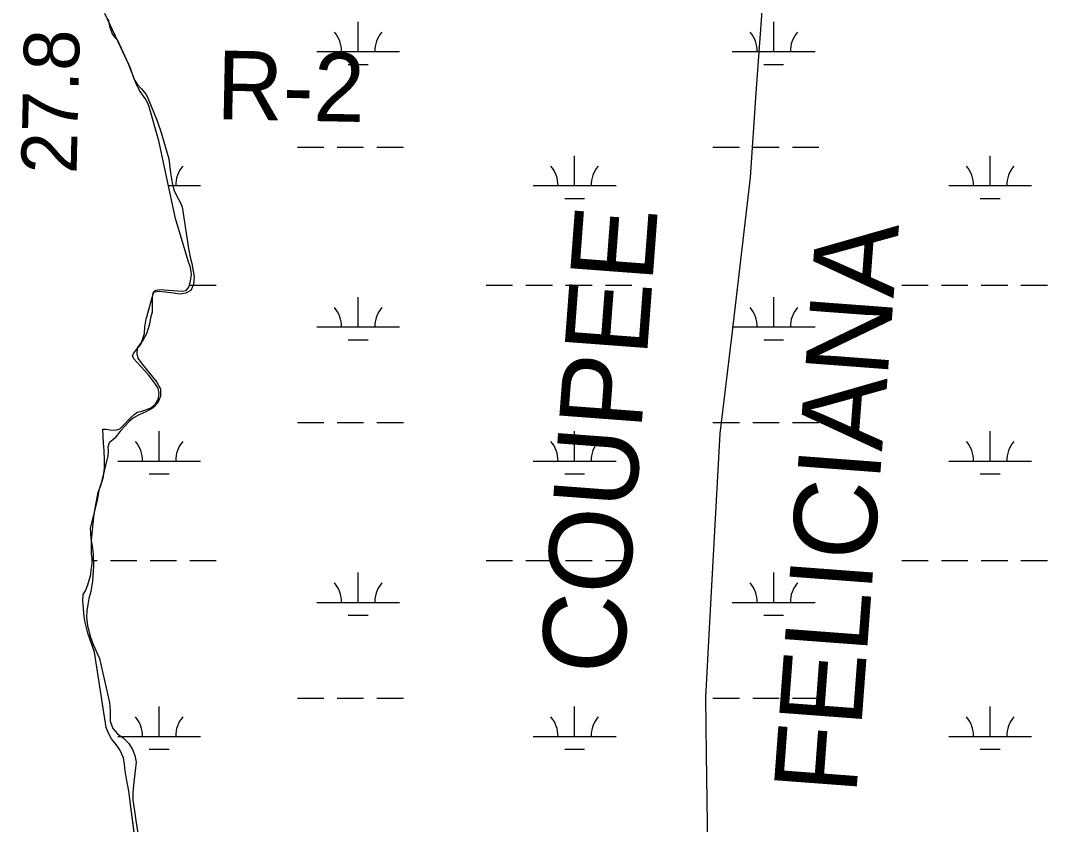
# Model space of a CAD drawing. Extents: x 3161564 to 3199464, y 849354 to 874788.
# Drawn here: x 3176988 to 3178229, y 863719 to 864690 of the extents above; entities that cross this region are included whole.
import ezdxf

# ---------------------------------------------------------------- set-up
doc = ezdxf.new("R2010")
doc.units = 0
for name, color, linetype in [('V-RIVR-RANG', 7, 'Continuous'), ('V-RIVR-RANG-IDEN', 7, 'Continuous'), ('V-SITE-VEGE', 7, 'Continuous'), ('V-TOPO-BNDY', 7, 'Continuous'), ('V-TOPO-GNAM-IDEN', 7, 'Continuous'), ('V-TOPO-SHOR', 7, 'Continuous'), ('V-WETL-SWMP', 7, 'Continuous')]:
    doc.layers.add(name, color=color, linetype=linetype)

msp = doc.modelspace()

# ---------------------------------------------------------------- linework, layer by layer
at = {"layer": 'V-SITE-VEGE'}
for p, q in [((3177094.1, 864691.9), (3177095.6, 864683.6)), ((3177095.6, 864683.6), (3177099, 864674.3)), ((3177099, 864674.3), (3177103, 864668.9)), ((3177103, 864668.9), (3177105.4, 864666.5)), ((3177105.4, 864666.5), (3177120.5, 864633.3)), ((3177120.5, 864633.3), (3177125.1, 864619.8)), ((3177125.1, 864619.8), (3177129.2, 864613.3)), ((3177129.2, 864613.3), (3177134.2, 864607.9)), ((3177134.2, 864607.9), (3177139.8, 864601)), ((3177139.8, 864601), (3177142.5, 864595.6)), ((3177142.5, 864595.6), (3177152.6, 864571)), ((3177152.6, 864571), (3177157.2, 864557.5)), ((3177157.2, 864557.5), (3177167.2, 864523.2)), ((3177167.2, 864523.2), (3177169.4, 864506.2)), ((3177169.4, 864506.2), (3177171.2, 864494.3)), ((3177171.2, 864494.3), (3177173.2, 864485.9)), ((3177173.2, 864485.9), (3177176.9, 864478)), ((3177176.9, 864478), (3177180.9, 864470.8)), ((3177180.9, 864470.8), (3177183.5, 864465.1)), ((3177183.5, 864465.1), (3177191, 864415)), ((3177191, 864415), (3177193, 864404.3)), ((3177193, 864404.3), (3177195.2, 864396.9)), ((3177195.2, 864396.9), (3177196.7, 864387.7)), ((3177196.7, 864387.7), (3177198.1, 864380.5)), ((3177198.1, 864380.5), (3177197, 864371.3)), ((3177197, 864371.3), (3177193.9, 864364.3)), ((3177147.3, 864354.9), (3177147.1, 864337.9)), ((3177147.9, 864361.2), (3177147.3, 864354.9)), ((3177150, 864362.1), (3177147.9, 864361.2)), ((3177156, 864363), (3177150, 864362.1)), ((3177173, 864361.1), (3177156, 864363)), ((3177180.7, 864359.8), (3177173, 864361.1)), ((3177187.7, 864360.9), (3177180.7, 864359.8)), ((3177193.9, 864364.3), (3177187.7, 864360.9)), ((3177145.4, 864331.1), (3177144.1, 864323.6)), ((3177147.1, 864337.9), (3177145.4, 864331.1)), ((3177144.1, 864323.6), (3177140.5, 864312)), ((3177136.5, 864304.5), (3177129.2, 864294.8)), ((3177140.5, 864312), (3177136.5, 864304.5)), ((3177129.2, 864294.8), (3177128.8, 864287.7)), ((3177128.8, 864287.7), (3177130, 864282.6)), ((3177130, 864282.6), (3177135.3, 864275.3)), ((3177135.3, 864275.3), (3177152.9, 864253.3)), ((3177152.9, 864253.3), (3177157.1, 864245.3)), ((3177157.1, 864245.3), (3177157.3, 864236.6)), ((3177157.3, 864236.6), (3177154, 864228.5)), ((3177139.4, 864217.8), (3177132.2, 864214.4)), ((3177148.3, 864222.4), (3177139.4, 864217.8)), ((3177154, 864228.5), (3177148.3, 864222.4)), ((3177119.6, 864205.9), (3177114.1, 864200.4)), ((3177124.5, 864210.2), (3177119.6, 864205.9)), ((3177132.2, 864214.4), (3177124.5, 864210.2)), ((3177109, 864194.6), (3177102.1, 864185.9)), ((3177114.1, 864200.4), (3177109, 864194.6)), ((3177095.2, 864180), (3177093.5, 864175.1)), ((3177102.1, 864185.9), (3177095.2, 864180)), ((3177093.5, 864175.1), (3177093.9, 864170.7)), ((3177093.9, 864170.7), (3177093.8, 864164.3)), ((3177093.8, 864164.3), (3177085.8, 864131.6)), ((3177085.8, 864131.6), (3177082.9, 864122.9)), ((3177082.9, 864122.9), (3177080.8, 864110.5)), ((3177080.8, 864110.5), (3177072.5, 864077.1)), ((3177072.5, 864077.1), (3177073.2, 864064.2)), ((3177073.2, 864064.2), (3177074.7, 864055.8)), ((3177074.7, 864055.8), (3177076.1, 864046)), ((3177076.1, 864046), (3177076.4, 864031.3)), ((3177076.4, 864031.3), (3177075.3, 864012.9)), ((3177075.3, 864012.9), (3177073.1, 864000.6)), ((3177073.1, 864000.6), (3177070.7, 863992.1)), ((3177069.4, 863984.8), (3177068.2, 863977.3)), ((3177070.7, 863992.1), (3177069.4, 863984.8)), ((3177068.2, 863977.3), (3177067.9, 863970.1)), ((3177067.9, 863970.1), (3177069.1, 863959.1)), ((3177069.1, 863959.1), (3177072.8, 863945.4)), ((3177072.8, 863945.4), (3177075.8, 863936.7)), ((3177075.8, 863936.7), (3177083.5, 863919.6)), ((3177083.5, 863919.6), (3177095.7, 863866.4)), ((3177095.7, 863866.4), (3177096.3, 863857)), ((3177096.3, 863857), (3177096.5, 863843.9)), ((3177096.5, 863843.9), (3177099.6, 863834.9)), ((3177099.6, 863834.9), (3177105.5, 863828.7)), ((3177105.5, 863828.7), (3177112.2, 863823.6)), ((3177112.2, 863823.6), (3177119, 863816.9)), ((3177119, 863816.9), (3177123.6, 863809.9)), ((3177123.6, 863809.9), (3177126.1, 863802.6)), ((3177126.1, 863802.6), (3177127.7, 863794.6)), ((3177126.6, 863784), (3177124.9, 863770.4)), ((3177127.7, 863794.6), (3177126.6, 863784)), ((3177124.9, 863770.4), (3177123.9, 863757.8)), ((3177123.9, 863757.8), (3177124, 863748.5)), ((3177124, 863748.5), (3177125.7, 863735.5)), ((3177125.7, 863735.5), (3177127.4, 863723.8)), ((3177127.4, 863723.8), (3177138.6, 863652.9))]:
    msp.add_line(p, q, dxfattribs=at)
at = {"layer": 'V-TOPO-BNDY'}
for p, q in [((3177876.8, 864602.9), (3177891.7, 864811.7)), ((3177869.7, 864500.6), (3177876.8, 864602.9)), ((3177847.2, 864307.9), (3177869.7, 864500.6)), ((3177833.3, 864191.3), (3177847.2, 864307.9)), ((3177819.9, 863948.6), (3177833.3, 864191.3)), ((3177815.8, 863872.5), (3177819.9, 863948.6)), ((3177816.7, 863804.9), (3177815.8, 863872.5)), ((3177821.5, 863468.4), (3177816.7, 863804.9))]:
    msp.add_line(p, q, dxfattribs=at)
at = {"layer": 'V-TOPO-SHOR'}
msp.add_lwpolyline([(3177134.6, 863640.7), (3177120.7, 863746.4), (3177118.9, 863759.8), (3177116.6, 863771.9), (3177114.8, 863783.8), (3177113.8, 863792.1), (3177112.7, 863799.8), (3177108.2, 863809.5), (3177103.7, 863815.9), (3177098.2, 863822.7), (3177094.3, 863829.3), (3177091.8, 863836.3), (3177077.6, 863927.3), (3177069.6, 863950.2), (3177066.2, 863963.1), (3177065, 863970.2), (3177063.6, 863989.3), (3177064, 863997.1), (3177066.5, 864001.4), (3177069.6, 864008.7), (3177073.1, 864021.2), (3177073.6, 864026.8), (3177074, 864028.4), (3177074.6, 864034.9), (3177074.6, 864041), (3177074.1, 864045.9), (3177073.9, 864062.2), (3177076.9, 864090.9), (3177077.6, 864096.5), (3177079.6, 864107.7), (3177082, 864120.4), (3177085.3, 864128.6), (3177088.3, 864139.5), (3177089.7, 864149.6), (3177089.8, 864159.3), (3177089.3, 864170.8), (3177088.4, 864179.7), (3177087.5, 864196.7), (3177091.5, 864196.8), (3177096.1, 864195.7), (3177102.4, 864195.5), (3177108, 864197.1), (3177111.7, 864200.5), (3177120.9, 864210.2), (3177125.9, 864214.8), (3177129.6, 864217.1), (3177134.7, 864218.3), (3177139.7, 864219.9), (3177145.6, 864222.4), (3177150.7, 864226.4), (3177154.5, 864232.7), (3177155.5, 864239.9), (3177154.4, 864246), (3177151.4, 864251.2), (3177142.9, 864262.2), (3177124.9, 864281.6), (3177123.5, 864285.1), (3177124.9, 864288.9), (3177133.7, 864299.1), (3177137.8, 864312.4), (3177138.3, 864320.2), (3177139.8, 864329.8), (3177140.9, 864332.5), (3177149.1, 864362.9), (3177151.5, 864364.5), (3177156.3, 864365.5), (3177183.1, 864363.3), (3177188.1, 864364.2), (3177191.6, 864368.4), (3177193.6, 864375.4), (3177194.6, 864383.4), (3177193.7, 864392.1), (3177190.9, 864400), (3177175.4, 864451), (3177155.4, 864544.9), (3177143.7, 864585.9), (3177141.8, 864590.5), (3177138.8, 864596), (3177132, 864605.8), (3177127.7, 864614.1), (3177118.3, 864638.8), (3177090, 864698.7)], dxfattribs=at)
at = {"layer": 'V-WETL-SWMP'}
for p, q in [((3177118.3, 864638.8), (3177090, 864698.7)), ((3177396, 864652.7), (3177396, 864688.7)), ((3177897.9, 864652.7), (3177897.9, 864688.7)), ((3177346, 864652.7), (3177446, 864652.7)), ((3177847.9, 864652.7), (3177947.9, 864652.7)), ((3177127.7, 864614.1), (3177118.3, 864638.8)), ((3177384, 864637.3), (3177408, 864637.3)), ((3177885.9, 864637.3), (3177909.9, 864637.3)), ((3177132, 864605.8), (3177127.7, 864614.1)), ((3177138.8, 864596), (3177132, 864605.8)), ((3177141.8, 864590.5), (3177138.8, 864596)), ((3177143.7, 864585.9), (3177141.8, 864590.5)), ((3177155.4, 864544.9), (3177143.7, 864585.9)), ((3177175.4, 864451), (3177155.4, 864544.9)), ((3177322.6, 864537.3), (3177354.6, 864537.3)), ((3177370.6, 864537.3), (3177402.6, 864537.3)), ((3177418.6, 864537.3), (3177450.6, 864537.3)), ((3177824.5, 864537.3), (3177856.5, 864537.3)), ((3177872.5, 864537.3), (3177904.5, 864537.3)), ((3177920.5, 864537.3), (3177952.5, 864537.3)), ((3177657.5, 864490.9), (3177657.5, 864526.9)), ((3178159.4, 864490.9), (3178159.4, 864526.9)), ((3177166.9, 864490.9), (3177205.6, 864490.9)), ((3177607.5, 864490.9), (3177707.5, 864490.9)), ((3178109.4, 864490.9), (3178209.4, 864490.9)), ((3177645.5, 864475.4), (3177669.5, 864475.4)), ((3178147.4, 864475.4), (3178171.4, 864475.4)), ((3177190.9, 864400), (3177175.4, 864451)), ((3177193.7, 864392.1), (3177190.9, 864400)), ((3177194.6, 864383.4), (3177193.7, 864392.1)), ((3177193.6, 864375.4), (3177194.6, 864383.4)), ((3177188.1, 864364.2), (3177191.6, 864368.4)), ((3177191.6, 864368.4), (3177193.6, 864375.4)), ((3177192.7, 864370.8), (3177224.7, 864370.8)), ((3177550.6, 864370.8), (3177582.6, 864370.8)), ((3177598.6, 864370.8), (3177630.6, 864370.8)), ((3177646.6, 864370.8), (3177678.6, 864370.8)), ((3177694.6, 864370.8), (3177726.6, 864370.8)), ((3178052.5, 864370.8), (3178084.5, 864370.8)), ((3178100.5, 864370.8), (3178132.5, 864370.8)), ((3178148.5, 864370.8), (3178180.5, 864370.8)), ((3178196.5, 864370.8), (3178228.5, 864370.8)), ((3177140.9, 864332.5), (3177149.1, 864362.9)), ((3177149.1, 864362.9), (3177151.5, 864364.5)), ((3177151.5, 864364.5), (3177156.3, 864365.5)), ((3177156.3, 864365.5), (3177183.1, 864363.3)), ((3177183.1, 864363.3), (3177188.1, 864364.2)), ((3177396, 864320.1), (3177396, 864356.1)), ((3177897.9, 864320.1), (3177897.9, 864356.1)), ((3177138.3, 864320.2), (3177139.8, 864329.8)), ((3177139.8, 864329.8), (3177140.9, 864332.5)), ((3177137.8, 864312.4), (3177138.3, 864320.2)), ((3177346, 864320.1), (3177446, 864320.1)), ((3177847.9, 864320.1), (3177947.9, 864320.1)), ((3177133.7, 864299.1), (3177137.8, 864312.4)), ((3177384, 864304.6), (3177408, 864304.6)), ((3177885.9, 864304.6), (3177909.9, 864304.6)), ((3177124.9, 864288.9), (3177133.7, 864299.1)), ((3177123.6, 864285.1), (3177124.9, 864288.9)), ((3177124.9, 864281.6), (3177123.6, 864285.1)), ((3177142.9, 864262.2), (3177124.9, 864281.6)), ((3177151.4, 864251.2), (3177142.9, 864262.2)), ((3177154.4, 864246), (3177151.4, 864251.2)), ((3177155.5, 864239.9), (3177154.4, 864246)), ((3177150.7, 864226.4), (3177154.5, 864232.7)), ((3177154.5, 864232.7), (3177155.5, 864239.9)), ((3177125.9, 864214.8), (3177129.6, 864217.1)), ((3177129.6, 864217.1), (3177134.7, 864218.3)), ((3177134.7, 864218.3), (3177139.7, 864219.9)), ((3177139.7, 864219.9), (3177145.6, 864222.4)), ((3177145.6, 864222.4), (3177150.7, 864226.4)), ((3177111.7, 864200.5), (3177120.9, 864210.2)), ((3177120.9, 864210.2), (3177125.9, 864214.8)), ((3177322.6, 864204.6), (3177354.6, 864204.6)), ((3177370.6, 864204.6), (3177402.6, 864204.6)), ((3177418.6, 864204.6), (3177450.6, 864204.6)), ((3177824.5, 864204.6), (3177856.5, 864204.6)), ((3177872.5, 864204.6), (3177904.5, 864204.6)), ((3177920.5, 864204.6), (3177952.5, 864204.6)), ((3177087.5, 864196.7), (3177091.5, 864196.8)), ((3177088.4, 864179.7), (3177087.5, 864196.7)), ((3177091.5, 864196.8), (3177096.1, 864195.7)), ((3177096.1, 864195.7), (3177102.4, 864195.5)), ((3177102.4, 864195.5), (3177108, 864197.1)), ((3177108, 864197.1), (3177111.7, 864200.5)), ((3177155.6, 864158.2), (3177155.6, 864194.2)), ((3177657.5, 864158.2), (3177657.5, 864194.2)), ((3178159.4, 864158.2), (3178159.4, 864194.2)), ((3177089.3, 864170.8), (3177088.4, 864179.7)), ((3177089.8, 864159.3), (3177089.3, 864170.8)), ((3177089.7, 864149.6), (3177089.8, 864159.3)), ((3177105.6, 864158.2), (3177205.6, 864158.2)), ((3177607.5, 864158.2), (3177707.5, 864158.2)), ((3178109.4, 864158.2), (3178209.4, 864158.2)), ((3177088.3, 864139.5), (3177089.7, 864149.6)), ((3177143.6, 864142.8), (3177167.6, 864142.8)), ((3177645.5, 864142.8), (3177669.5, 864142.8)), ((3178147.4, 864142.8), (3178171.4, 864142.8)), ((3177085.3, 864128.6), (3177088.3, 864139.5)), ((3177079.6, 864107.7), (3177082.1, 864120.4)), ((3177082.1, 864120.4), (3177085.3, 864128.6)), ((3177077.6, 864096.5), (3177079.6, 864107.7)), ((3177076.9, 864090.9), (3177077.6, 864096.5)), ((3177073.9, 864062.2), (3177076.9, 864090.9)), ((3177074.1, 864045.9), (3177073.9, 864062.2)), ((3177074.6, 864041), (3177074.1, 864045.9)), ((3177074, 864028.4), (3177074.6, 864034.9)), ((3177074.6, 864034.9), (3177074.6, 864041)), ((3177074.6, 864038.1), (3177080.7, 864038.1)), ((3177096.7, 864038.1), (3177128.7, 864038.1)), ((3177144.7, 864038.1), (3177176.7, 864038.1)), ((3177192.7, 864038.1), (3177224.7, 864038.1)), ((3177550.6, 864038.1), (3177582.6, 864038.1)), ((3177598.6, 864038.1), (3177630.6, 864038.1)), ((3177646.6, 864038.1), (3177678.6, 864038.1)), ((3177694.6, 864038.1), (3177726.6, 864038.1)), ((3178052.5, 864038.1), (3178084.5, 864038.1)), ((3178100.5, 864038.1), (3178132.5, 864038.1)), ((3178148.5, 864038.1), (3178180.5, 864038.1)), ((3178196.5, 864038.1), (3178228.5, 864038.1)), ((3177069.6, 864008.7), (3177073.1, 864021.2)), ((3177073.1, 864021.2), (3177073.6, 864026.8)), ((3177073.6, 864026.8), (3177074, 864028.4)), ((3177396, 863987.4), (3177396, 864023.4)), ((3177897.9, 863987.4), (3177897.9, 864023.4)), ((3177066.5, 864001.4), (3177069.6, 864008.7)), ((3177063.6, 863989.3), (3177064, 863997.1)), ((3177064, 863997.1), (3177066.5, 864001.4)), ((3177065, 863970.2), (3177063.6, 863989.3)), ((3177346, 863987.4), (3177446, 863987.4)), ((3177847.9, 863987.4), (3177947.9, 863987.4)), ((3177066.2, 863963.1), (3177065, 863970.2)), ((3177384, 863971.9), (3177408, 863971.9)), ((3177885.9, 863971.9), (3177909.9, 863971.9)), ((3177069.6, 863950.2), (3177066.2, 863963.1)), ((3177077.6, 863927.3), (3177069.6, 863950.2)), ((3177091.8, 863836.3), (3177077.6, 863927.3)), ((3177322.6, 863871.9), (3177354.6, 863871.9)), ((3177370.6, 863871.9), (3177402.6, 863871.9)), ((3177418.6, 863871.9), (3177450.6, 863871.9)), ((3177824.5, 863871.9), (3177856.5, 863871.9)), ((3177872.5, 863871.9), (3177904.5, 863871.9)), ((3177920.5, 863871.9), (3177952.5, 863871.9)), ((3177155.6, 863825.5), (3177155.6, 863861.5)), ((3177657.5, 863825.5), (3177657.5, 863861.5)), ((3178159.4, 863825.5), (3178159.4, 863861.5)), ((3177094.3, 863829.3), (3177091.8, 863836.3)), ((3177098.2, 863822.7), (3177094.3, 863829.3)), ((3177103.7, 863815.9), (3177098.2, 863822.7)), ((3177105.6, 863825.5), (3177205.6, 863825.5)), ((3177607.5, 863825.5), (3177707.5, 863825.5)), ((3178109.4, 863825.5), (3178209.4, 863825.5)), ((3177108.2, 863809.5), (3177103.7, 863815.9)), ((3177112.7, 863799.8), (3177108.2, 863809.5)), ((3177143.6, 863810.1), (3177167.6, 863810.1)), ((3177645.5, 863810.1), (3177669.5, 863810.1)), ((3178147.4, 863810.1), (3178171.4, 863810.1)), ((3177113.8, 863792.1), (3177112.7, 863799.8)), ((3177114.8, 863783.8), (3177113.8, 863792.1)), ((3177116.6, 863771.9), (3177114.8, 863783.8)), ((3177118.9, 863759.8), (3177116.6, 863771.9)), ((3177120.7, 863746.4), (3177118.9, 863759.8)), ((3177134.6, 863640.7), (3177120.7, 863746.4))]:
    msp.add_line(p, q, dxfattribs=at)
for centre, start, end in [((3177340.8, 864653.2), 359.2282, 40.7718), ((3177451.3, 864653.2), 139.2282, 180.7718), ((3177842.7, 864653.2), 359.2282, 40.7718), ((3177953.2, 864653.2), 139.2282, 180.7718), ((3177210.8, 864491.3), 139.2282, 180.7718), ((3177602.2, 864491.3), 359.2282, 40.7718), ((3177712.7, 864491.3), 139.2282, 180.7718), ((3178104.1, 864491.3), 359.2282, 40.7718), ((3178214.6, 864491.3), 139.2282, 180.7718), ((3177340.8, 864320.5), 359.2282, 40.7718), ((3177451.3, 864320.5), 139.2282, 180.7718), ((3177842.7, 864320.5), 359.2282, 40.7718), ((3177953.2, 864320.5), 139.2282, 180.7718), ((3177100.3, 864158.7), 359.2282, 40.7718), ((3177210.8, 864158.7), 139.2282, 180.7718), ((3177602.2, 864158.7), 359.2282, 40.7718), ((3177712.7, 864158.7), 139.2282, 180.7718), ((3178104.1, 864158.7), 359.2282, 40.7718), ((3178214.6, 864158.7), 139.2282, 180.7718), ((3177340.8, 863987.9), 359.2282, 40.7718), ((3177451.3, 863987.9), 139.2282, 180.7718), ((3177842.7, 863987.9), 359.2282, 40.7718), ((3177953.2, 863987.9), 139.2282, 180.7718), ((3177100.3, 863826), 359.2282, 40.7718), ((3177210.8, 863826), 139.2282, 180.7718), ((3177602.2, 863826), 359.2282, 40.7718), ((3177712.7, 863826), 139.2282, 180.7718), ((3178104.1, 863826), 359.2282, 40.7718), ((3178214.6, 863826), 139.2282, 180.7718)]:
    msp.add_arc(centre, 35.2, start, end, dxfattribs=at)

# ---------------------------------------------------------------- texts
at = {"layer": 'V-RIVR-RANG'}
msp.add_text('27.8', height=67, rotation=88.7383, dxfattribs=at).set_placement((3177055.9, 864504.6))
at = {"layer": 'V-RIVR-RANG-IDEN'}
msp.add_text('R-2', height=83, rotation=358.8779, dxfattribs=at).set_placement((3177224.4, 864571.2))
at = {"layer": 'V-TOPO-GNAM-IDEN'}
for s, p in [('COUPEE', (3177715.7, 863898.4)), ('FELICIANA', (3177997.5, 863754.2))]:
    msp.add_text(s, height=100, rotation=85.7038, dxfattribs=at).set_placement(p)

doc.saveas('drawing.dxf')
